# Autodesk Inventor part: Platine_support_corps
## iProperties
Shininess: 64.0
Length Units: 11269
Angle Units: 11279
Time Units: 11290
Mass Units: 11283
Length Display Precision: 3
Angle Display Precision: 2
Compacted: True
Part Number: Platine_support_corps
Document SubType Name: Modeling
Created: 2008-02
Material: Par défaut
Designer: Pascal
Density: 0.0
Volumn: 0.0
Area: 0.0
PropertySet Name: Model Information
Control State: 0
Master: False
Checked Out: False
DESIGNATION: pièce
Author: Pascal
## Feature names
1. Extrusion1
2. Chanfrein1 [Chamfer]
3. Extrusion2
4. Réseau rectangulaire1 [Rectangular Pattern]
